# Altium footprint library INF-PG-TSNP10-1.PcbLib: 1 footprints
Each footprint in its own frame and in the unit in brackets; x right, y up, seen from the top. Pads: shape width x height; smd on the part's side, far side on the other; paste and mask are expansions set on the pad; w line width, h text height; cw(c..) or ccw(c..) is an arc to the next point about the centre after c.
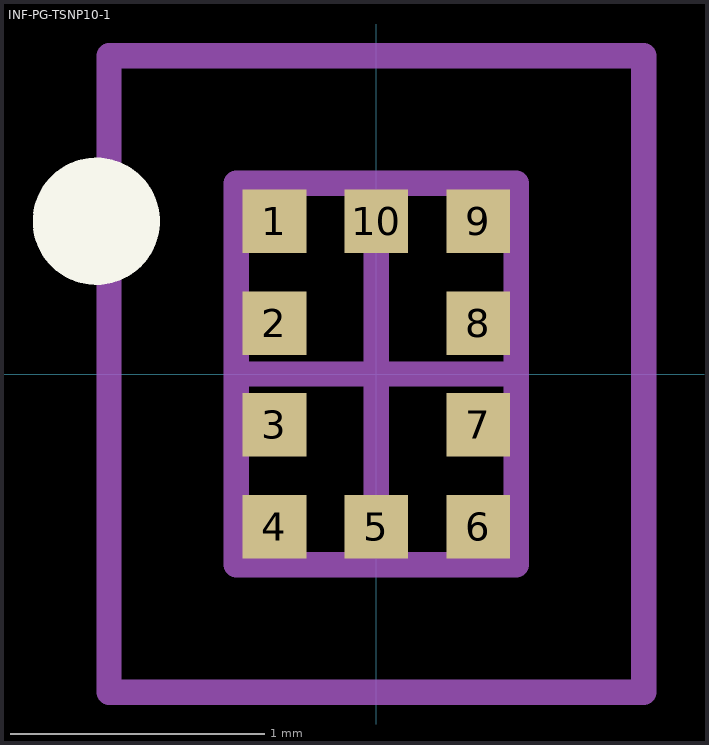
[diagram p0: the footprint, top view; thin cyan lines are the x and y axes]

## INF-PG-TSNP10-1 [mm] "TSNP10-1,0.40mm Pitch, 10 Pin, 1.10mm W X 1.50mm L X 0.4mm H body"
height 0.4
pads (10):
  rect 0.25x0.25 smd paste+0 mask+0: 1(-0.4,0.6) 2(-0.4,0.2) 3(-0.4,-0.2) 4(-0.4,-0.6) 5(0,-0.6) 6(0.4,-0.6) 7(0.4,-0.2) 8(0.4,0.2) 9(0.4,0.6) 10(0,0.6)
Top Overlay:
  circle w0.25: c-1.1,0.6 r0.125
Mechanical 3:
  text ".DESIGNATOR" at 0,0 h1.2
Mechanical 13:
  lines w0.1: -0.55,-0.75 -0.55,0.75 0.55,0.75 0.55,-0.75 -0.55,-0.75
Mechanical 15:
  lines w0.1: -0.5,0 0.5,0 ; 0,-0.5 0,0.5 ; -1.05,-1.25 -1.05,1.25 1.05,1.25 1.05,-1.25 -1.05,-1.25
3D body: height 0.4, standoff 0, extent -0.55,-0.75 0.55,0.75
